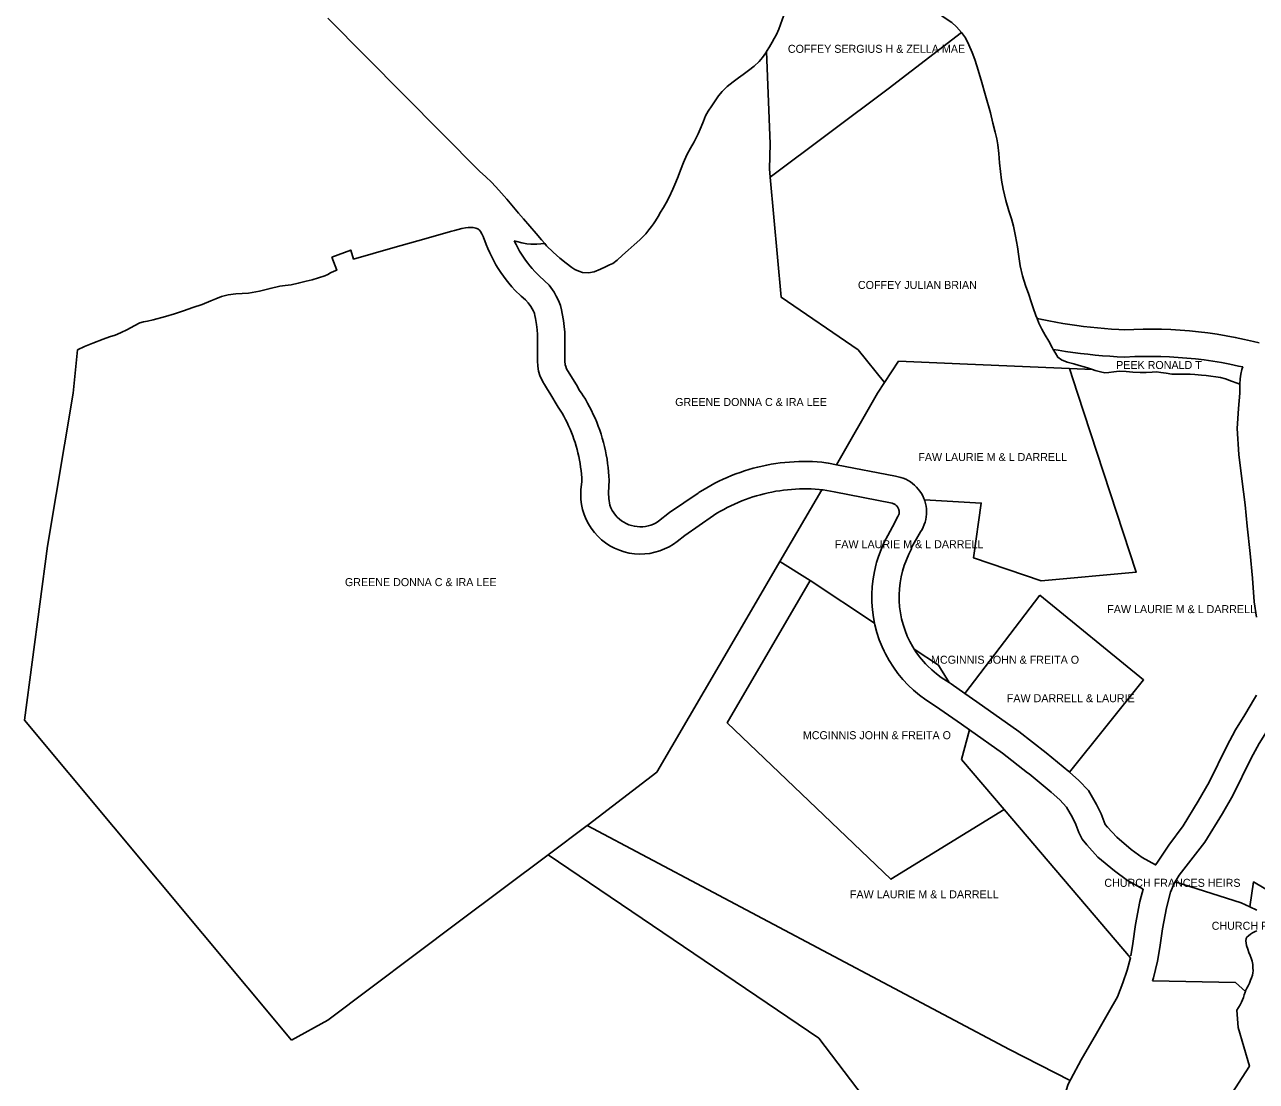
# Model space of a CAD drawing. Extents: x 1249333 to 1254314, y 856599 to 862241.
# Drawn here: x 1249333 to 1252043, y 858486 to 860811 of the extents above; entities that cross this region are included whole.
import ezdxf

# ---------------------------------------------------------------- set-up
doc = ezdxf.new("R2010")
doc.units = 0
doc.layers.add('Old_Level_12', color=7, linetype='Continuous')
doc.layers.add('Old_Level_32', color=7, linetype='Continuous')

msp = doc.modelspace()

# ---------------------------------------------------------------- linework, layer by layer
at = {"layer": 'Old_Level_12'}
for p, q in [((1251407.875, 860064), (1251631.875, 860054.5)), ((1251631.875, 860054.5), (1251682.25, 860052.375)), ((1251087.25, 859787.625), (1250994.875, 859629.563)), ((1249382.625, 859663.688), (1249332.625, 859280.875)), ((1250994.875, 859629.563), (1251061.375, 859587.625)), ((1251061.375, 859587.625), (1251203, 859494.438)), ((1251401.75, 859339.313), (1251567, 859556.063)), ((1251348.375, 859394.438), (1251367.125, 859363.313)), ((1249332.625, 859280.875), (1249920, 858576.75)), ((1251487.875, 859083.75), (1251765.875, 858757.5)), ((1250570.75, 859048.688), (1250484.75, 858984.188)), ((1250286.875, 858835.813), (1250484.75, 858984.188))]:
    msp.add_line(p, q, dxfattribs=at)
for points in [[(1251142.625, 860976.438), (1251152.25, 860975.5), (1251163.5, 860972.063), (1251178.625, 860965.188), (1251190.375, 860958.25), (1251203.125, 860949.625), (1251216.625, 860940.625), (1251228.625, 860932.688), (1251239.875, 860925.25), (1251250.5, 860917.875), (1251261.75, 860909.563), (1251274.375, 860899.25), (1251293.125, 860882.5), (1251308.5, 860867.688), (1251325.875, 860851.688), (1251335.5, 860843.313), (1251344.375, 860835.875), (1251353.125, 860829.313), (1251363, 860822.75), (1251373.125, 860815.563), (1251383.5, 860806.125), (1251394.25, 860794.188)], [(1251026.125, 860872.813), (1251025.25, 860871.688), (1251017.875, 860860.875), (1251009.625, 860846.875), (1251005.125, 860837.563), (1251002.375, 860829.625), (1251000, 860822.125), (1250996.375, 860811.813), (1250992, 860800.938), (1250986.875, 860789.688), (1250982.25, 860780.688), (1250977.5, 860772.438), (1250971.625, 860762.5), (1250965.25, 860751.75)], [(1250000, 860825.125), (1250334.25, 860488.25), (1250346.875, 860476.875), (1250360.5, 860463.75), (1250376.25, 860447.063), (1250394, 860426.813), (1250408.25, 860409.625), (1250419.375, 860396.25), (1250430.375, 860383.813), (1250444.25, 860368.063), (1250458.25, 860351.875), (1250469.75, 860337.875), (1250477.125, 860329.5)], [(1251394.25, 860794.188), (1251233.125, 860670.188), (1250973.625, 860475.375)], [(1251394.25, 860794.188), (1251402.875, 860782.125), (1251410.625, 860766.938), (1251417.875, 860749.563), (1251423.5, 860734.5), (1251428.25, 860720.563), (1251437.75, 860689.313), (1251447.5, 860655.563), (1251457.875, 860617), (1251463.5, 860594.5), (1251468.375, 860574.563), (1251471.875, 860560.188), (1251474.125, 860546.563), (1251476.375, 860527.563), (1251478.25, 860507.438), (1251480.125, 860487.75), (1251482.5, 860469.25), (1251486.25, 860449.438), (1251492.25, 860424.375), (1251498.75, 860401.25), (1251504.25, 860383.875), (1251508.75, 860367.438), (1251511, 860356.875), (1251513.375, 860345.5), (1251517.375, 860322.313), (1251520.5, 860300.688), (1251523.75, 860280.188), (1251528.625, 860258.688), (1251535.375, 860237.188), (1251542.5, 860217.125), (1251547.875, 860201.125), (1251552.125, 860187.75), (1251557.875, 860171.125), (1251560.5, 860164.688)], [(1250477.125, 860329.5), (1250481.375, 860324.5), (1250495.75, 860310.313), (1250510.75, 860297.375), (1250524.375, 860286.5), (1250536.625, 860277.125), (1250543.5, 860272.563), (1250551.875, 860268.438), (1250560.625, 860265.5), (1250573.125, 860264.688), (1250585.75, 860267.563), (1250599.75, 860273.125), (1250610.625, 860278), (1250620, 860282.375), (1250627, 860285.875), (1250636.75, 860293), (1250648.5, 860303.75), (1250660.5, 860315.063), (1250673.625, 860326.438), (1250686.125, 860337.375), (1250699.375, 860351.063), (1250706.25, 860359.313), (1250712.125, 860366.75), (1250716.5, 860372.688), (1250721, 860379.688), (1250726.5, 860388.813), (1250732.125, 860398.25), (1250738.5, 860408.75), (1250744.5, 860419.063), (1250750.875, 860431.438), (1250759.125, 860448.938), (1250765.875, 860464.25), (1250770.875, 860477), (1250776.125, 860491.125), (1250782.75, 860508), (1250790.125, 860524.625), (1250797.75, 860539.25), (1250805.75, 860553.625), (1250814.5, 860571), (1250821.125, 860586.125), (1250826.375, 860599.125), (1250831.25, 860610.188), (1250837.125, 860620.688), (1250844.75, 860632.375), (1250852.5, 860643.75), (1250859.625, 860654.188), (1250867.625, 860664.125), (1250878.875, 860674.938), (1250892, 860685.688), (1250903.25, 860693.938), (1250914, 860701.375), (1250925.875, 860709.938), (1250938, 860719.563), (1250948.875, 860729.75), (1250956.75, 860739), (1250963.875, 860749.5), (1250965.25, 860751.75)], [(1250965.25, 860751.75), (1250973.625, 860548.625), (1250972, 860493.813), (1250973.625, 860475.375)], [(1250973.625, 860475.375), (1250997.625, 860211.125), (1251167.125, 860095.563), (1251225, 860023.375)], [(1250008.625, 860299.438), (1250050.25, 860315.188), (1250056.375, 860295.313), (1250143.125, 860319.938), (1250197.75, 860335.5), (1250272.875, 860356.813), (1250278.5, 860358.25), (1250286.625, 860360.688), (1250294.75, 860362.563), (1250303, 860363.938), (1250308.875, 860364.75), (1250313.125, 860364.75), (1250320, 860364.438), (1250325.375, 860363.125), (1250329.625, 860361.5), (1250333.375, 860358.813), (1250335.625, 860356.313), (1250338.875, 860350.813), (1250342.25, 860343.75), (1250342.5, 860343.125), (1250345.5, 860335.75), (1250348.5, 860327.563), (1250352.25, 860318.25), (1250356.25, 860309.188), (1250360.5, 860300.25)], [(1250477.125, 860329.5), (1250459.75, 860328.188), (1250446.625, 860327.875), (1250438.125, 860328.938), (1250427.125, 860331.375), (1250415.875, 860334.313), (1250410.125, 860335.813)], [(1250487, 860237.875), (1250465.625, 860258.063), (1250460.75, 860262.625), (1250455.25, 860268.25), (1250449.875, 860274.25), (1250444.5, 860280.375), (1250439.625, 860286.563), (1250434.875, 860292.938), (1250430.25, 860299.5), (1250426, 860306.188), (1250421.875, 860313), (1250417.875, 860320), (1250414.25, 860327.125), (1250410.75, 860334.313), (1250410.125, 860335.813)], [(1250008.625, 860299.438), (1250019.625, 860270.563), (1250014.125, 860268.375), (1250006, 860264.688), (1250000, 860261.438), (1249993.125, 860258.75), (1249979.625, 860254.313), (1249965.625, 860249.688), (1249952.125, 860246.375), (1249934.75, 860241.938), (1249919, 860238.688), (1249906.125, 860237.063), (1249894.375, 860235.563), (1249872.875, 860230.875), (1249849.625, 860224.938), (1249825.25, 860220.375), (1249811, 860219.25), (1249797.25, 860218.5), (1249780.875, 860216.375), (1249765.75, 860212.688), (1249753.625, 860208.125), (1249742.375, 860203.188), (1249723.375, 860195.688), (1249703, 860188.563), (1249682.5, 860181.563), (1249662.75, 860174.875), (1249642.875, 860168.875), (1249615.25, 860161.563), (1249603.125, 860158.813), (1249594.125, 860156.938), (1249586.5, 860154.75), (1249573.375, 860148.688), (1249559.125, 860140.625), (1249543.625, 860132.75), (1249531.5, 860127.938), (1249519.75, 860124.063), (1249505.625, 860119.188), (1249483, 860110.438)], [(1250360.5, 860300.25), (1250365.125, 860291.5), (1250369.875, 860282.875), (1250375, 860274.313), (1250380.5, 860266), (1250386.125, 860257.813), (1250392.125, 860249.813), (1250398.5, 860242), (1250404.875, 860234.5), (1250411.5, 860227.25), (1250425.5, 860213.375), (1250434.625, 860205.688), (1250440.75, 860199.375), (1250446.875, 860190.75), (1250449.625, 860185.688), (1250452.25, 860180.563), (1250453.625, 860177.688), (1250454.375, 860175.625), (1250455.5, 860171.063), (1250456.75, 860164.625), (1250458.75, 860151.688), (1250460.375, 860139.813), (1250461.375, 860129.438), (1250461.375, 860071.5), (1250462.125, 860059.813), (1250463.75, 860048.5), (1250466.625, 860038.938), (1250473, 860025.25), (1250476.75, 860018.938), (1250483.375, 860008.563), (1250488.5, 860000), (1250507, 859969.75), (1250511.25, 859963.063), (1250515.25, 859956.313), (1250519.125, 859949.438), (1250522.875, 859942.5), (1250526.5, 859935.438), (1250529.75, 859928.313), (1250533, 859921.063), (1250536, 859913.75), (1250538.875, 859906.5), (1250541.5, 859899.063), (1250544, 859891.5), (1250546.375, 859883.875), (1250548.5, 859876.25), (1250550.375, 859868.75), (1250552.125, 859861), (1250553.75, 859853.125), (1250555.125, 859845.5), (1250556.25, 859837.563), (1250557.375, 859829.688), (1250558.125, 859821.875), (1250558.75, 859813.938), (1250559.125, 859805.938), (1250556.75, 859787.813), (1250556.375, 859777.75), (1250556.875, 859766.375), (1250558.125, 859755.125), (1250560.625, 859744), (1250564, 859733.063), (1250568.375, 859722.563), (1250573.5, 859712.563), (1250579.5, 859703), (1250586.375, 859693.813), (1250593.875, 859685.438), (1250602.125, 859677.688), (1250611.125, 859670.625), (1250620.75, 859664.313), (1250630.875, 859658.938), (1250641.375, 859654.5), (1250652.125, 859650.938), (1250663.125, 859648.375), (1250674.5, 859646.75), (1250685.875, 859646.125), (1250697.125, 859646.438), (1250708.5, 859647.688), (1250719.625, 859650), (1250730.5, 859653.25), (1250741, 859657.313), (1250751.25, 859662.375), (1250760.875, 859668.25), (1250768.375, 859673.563), (1250785.625, 859687), (1250848.875, 859731.188), (1250856.25, 859735.813), (1250863.75, 859740.25), (1250871.375, 859744.5), (1250879, 859748.563), (1250886.75, 859752.438), (1250894.625, 859756.125), (1250902.625, 859759.625), (1250910.625, 859762.938), (1250918.75, 859766.063), (1250926.875, 859769), (1250935.125, 859771.75), (1250943.375, 859774.313), (1250951.75, 859776.688), (1250960.125, 859778.875), (1250968.625, 859780.875), (1250977.125, 859782.688)], [(1251119.375, 859842.5), (1251101.625, 859846.125), (1251096.125, 859847.25), (1251086.625, 859848.188), (1251076.5, 859848.938), (1251066.375, 859849.5), (1251056.25, 859849.813), (1251046.125, 859849.875), (1251036, 859849.688), (1251025.875, 859849.25), (1251015.75, 859848.625), (1251005.625, 859847.75), (1250995.625, 859846.625), (1250985.625, 859845.25), (1250975.625, 859843.625), (1250965.625, 859841.813), (1250955.75, 859839.75), (1250945.875, 859837.438), (1250936.125, 859834.875), (1250926.375, 859832.125), (1250916.75, 859829.125), (1250907.125, 859825.938), (1250897.625, 859822.5), (1250888.25, 859818.813), (1250878.875, 859814.938), (1250869.625, 859810.813), (1250860.5, 859806.5), (1250851.5, 859801.938), (1250842.625, 859797.188), (1250833.75, 859792.25), (1250825, 859787.063), (1250818.5, 859783), (1250816.5, 859781.563), (1250814.625, 859780.313), (1250751.75, 859737.375), (1250727.625, 859718.25), (1250722.25, 859715), (1250716.75, 859712.313), (1250711, 859710), (1250705.125, 859708.25), (1250699, 859707.063), (1250692.875, 859706.313), (1250686.625, 859706.125), (1250680.5, 859706.5), (1250674.375, 859707.375), (1250668.375, 859708.813), (1250662.375, 859710.75), (1250656.625, 859713.188), (1250651.25, 859716.063), (1250646.125, 859719.375), (1250641.375, 859723.188), (1250636.875, 859727.438), (1250632.625, 859732.063), (1250629, 859736.875), (1250625.75, 859742.188), (1250622.875, 859747.813), (1250620.5, 859753.563), (1250617.875, 859768.313), (1250617.25, 859780.563), (1250619, 859808.563), (1250618.375, 859817.813), (1250617.75, 859827.125), (1250616.75, 859836.563), (1250615.625, 859845.813), (1250614.25, 859855), (1250612.625, 859864.375), (1250610.75, 859873.5), (1250608.75, 859882.625), (1250606.375, 859891.875), (1250603.75, 859900.875), (1250601.125, 859909.75), (1250598.125, 859918.563), (1250595, 859927.375), (1250591.625, 859936.25), (1250587.875, 859944.938), (1250584.125, 859953.438), (1250580, 859961.938), (1250575.875, 859970.25), (1250571.375, 859978.563), (1250566.75, 859986.688), (1250561.75, 859994.688), (1250557.75, 860000), (1250553.25, 860007), (1250549.125, 860014.625), (1250525.375, 860054.125), (1250523.25, 860059.25), (1250522.125, 860062.625), (1250521.625, 860070.5), (1250521.25, 860083.438), (1250521.25, 860134.25), (1250519.875, 860146.688), (1250518.25, 860160.313), (1250515.75, 860175.25), (1250514, 860183.938), (1250511.875, 860192.875), (1250509.125, 860200.563), (1250506.25, 860206.813), (1250502.625, 860213.938), (1250497.625, 860222.75), (1250487, 860237.875)], [(1251560.5, 860164.688), (1251564.625, 860154.375), (1251571.125, 860140.813), (1251578.25, 860128.063), (1251586.25, 860114.375), (1251593.875, 860101), (1251596.375, 860096.5)], [(1252049.375, 860110.813), (1252036.625, 860114.063), (1252016.875, 860118.625), (1251996.875, 860122.813), (1251976.75, 860126.563), (1251956.625, 860129.875), (1251936.25, 860132.813), (1251916.125, 860135.25), (1251895.75, 860137.313), (1251875.25, 860138.938), (1251854.875, 860140.063), (1251834.5, 860140.875), (1251814.125, 860141.188), (1251793.75, 860141.063), (1251773.375, 860140.563), (1251754, 860139.563), (1251740.25, 860140.25), (1251724.75, 860141.25), (1251709.375, 860142.375), (1251693.875, 860143.813), (1251678.5, 860145.375), (1251663.125, 860147.125), (1251647.875, 860149.188), (1251632.5, 860151.375), (1251617.125, 860153.813), (1251602, 860156.375), (1251586.75, 860159.25), (1251571.5, 860162.313), (1251560.5, 860164.688)], [(1249483, 860110.438), (1249464.625, 860102.563), (1249449.25, 860095.688)], [(1249449.25, 860095.688), (1249439.375, 860000), (1249382.625, 859663.688)], [(1251596.375, 860096.5), (1251607.375, 860094.563), (1251623.5, 860092), (1251639.625, 860089.688), (1251655.875, 860087.625), (1251672, 860085.75), (1251688.125, 860084.063), (1251704.375, 860082.625), (1251720.75, 860081.375), (1251737, 860080.375)], [(1251596.375, 860096.5), (1251600.875, 860088.5), (1251606.25, 860079.188), (1251614.125, 860073.375), (1251627.125, 860068.75), (1251641.375, 860064.813), (1251653.125, 860061.438), (1251664, 860058.063), (1251675.75, 860054.375), (1251682.25, 860052.375)], [(1251737, 860080.375), (1251753.125, 860079.625), (1251775.625, 860080.563), (1251794.75, 860081.063), (1251813.875, 860081.188), (1251833, 860080.875), (1251852.125, 860080.188), (1251871.25, 860079.063), (1251890.25, 860077.563), (1251909.375, 860075.625), (1251928.5, 860073.313), (1251947.375, 860070.625), (1251966.25, 860067.438), (1251985.125, 860063.938), (1252003.875, 860060), (1252013.25, 860057.813), (1252011.375, 860052.375), (1252009.125, 860042.063), (1252007.375, 860031.5), (1252006.625, 860020)], [(1251225, 860023.375), (1251256, 860070.438), (1251407.875, 860064)], [(1251631.875, 860054.5), (1251649.75, 860000), (1251778.875, 859606.688), (1251570, 859587.313), (1251420.375, 859637.875), (1251437.75, 859758.25), (1251312.625, 859765.188)], [(1251682.25, 860052.375), (1251688.5, 860050.438), (1251700.375, 860047.063), (1251709.75, 860045.188), (1251718.375, 860045.5), (1251729.625, 860047), (1251741.375, 860048.375), (1251756.875, 860048.25), (1251771.5, 860046.75), (1251787.375, 860045.563), (1251801, 860045.813), (1251813.625, 860046.5), (1251823.375, 860046.813), (1251832.625, 860045.813), (1251844.625, 860043.938), (1251856.875, 860042.375), (1251866.875, 860041.875), (1251876.625, 860041.938), (1251887.25, 860042), (1251897.875, 860041.688), (1251907.75, 860041.25), (1251914.875, 860040.813), (1251922.25, 860040.125), (1251932.5, 860038.875), (1251943.25, 860037.563), (1251954.25, 860036.125), (1251964.5, 860034.375), (1251975.25, 860031.625), (1251988.625, 860026.875), (1252001, 860022), (1252006.625, 860020)], [(1251225, 860023.375), (1251209.25, 860000), (1251119.375, 859842.5)], [(1252006.625, 860020), (1252006.75, 860009.813), (1252006.875, 860000), (1252003.875, 859966.438), (1252000.75, 859922.5), (1252005, 859864.938), (1252011.125, 859811.75), (1252018.375, 859754.813), (1252023, 859707.813), (1252029.875, 859647.188), (1252034.625, 859593.375), (1252038.625, 859540.813), (1252043.75, 859507)], [(1251312.625, 859765.188), (1251311.375, 859768.75), (1251308.875, 859774.125), (1251306, 859779.313), (1251302.75, 859784.25), (1251299.25, 859788.938), (1251295.375, 859793.375), (1251291.125, 859797.5), (1251286.625, 859801.313), (1251281.875, 859804.813), (1251276.875, 859807.938), (1251271.625, 859810.688), (1251266.25, 859813), (1251260.625, 859814.938), (1251254.875, 859816.438), (1251249.125, 859817.5), (1251119.375, 859842.5)], [(1250977.125, 859782.688), (1250985.625, 859784.25), (1250994.25, 859785.625), (1251002.875, 859786.813), (1251011.5, 859787.813), (1251020.125, 859788.563), (1251028.75, 859789.125), (1251037.5, 859789.5), (1251046.25, 859789.688), (1251055, 859789.625), (1251063.75, 859789.375), (1251072.375, 859788.938), (1251081, 859788.25), (1251087.25, 859787.625)], [(1251087.25, 859787.625), (1251089.625, 859787.375), (1251114, 859782.75)], [(1251114, 859782.75), (1251241.875, 859757.875), (1251243.25, 859757.5), (1251244.625, 859757), (1251246, 859756.438), (1251247.25, 859755.75), (1251248.5, 859755), (1251249.75, 859754.125), (1251250.875, 859753.188), (1251251.875, 859752.125), (1251252.875, 859751), (1251253.75, 859749.813), (1251254.5, 859748.563), (1251255.25, 859747.25), (1251255.875, 859745.875), (1251256.375, 859744.5), (1251256.75, 859743.063), (1251257, 859741.625), (1251257.25, 859738.75), (1251257.25, 859737.25), (1251257.125, 859735.813), (1251256.875, 859734.375), (1251256.5, 859732.938), (1251256, 859731.563), (1251254.375, 859728.625), (1251242.5, 859705.813), (1251232.375, 859687.188), (1251224.5, 859672), (1251217.625, 859656.563), (1251211.625, 859640.688), (1251207.625, 859627.625), (1251206.625, 859624.375), (1251202.75, 859607.938), (1251199.75, 859591.375), (1251197.875, 859574.5), (1251197, 859557.5), (1251197.125, 859540.5), (1251198.375, 859523.563), (1251200.625, 859506.813), (1251203, 859494.438)], [(1251290.125, 859437.188), (1251287, 859442.125), (1251280.625, 859453.75), (1251274.875, 859465.813), (1251270, 859478.188), (1251265.75, 859490.813), (1251262.375, 859503.563), (1251259.875, 859516.563), (1251258.125, 859529.813), (1251257.125, 859543), (1251257.125, 859545.625), (1251257, 859556.25), (1251257.625, 859569.5), (1251259.25, 859582.625), (1251261.5, 859595.813), (1251264.625, 859608.75), (1251268.375, 859621.313), (1251273.125, 859633.813), (1251278.5, 859646), (1251284.625, 859657.688), (1251284.375, 859660.938), (1251304.25, 859694.813), (1251307.625, 859700.063), (1251310.25, 859705.375), (1251312.5, 859710.875), (1251314.375, 859716.5), (1251315.75, 859722.25), (1251316.75, 859728.063), (1251317.25, 859733.938), (1251317.375, 859739.875), (1251317, 859745.813), (1251316.25, 859751.688), (1251315, 859757.5), (1251313.375, 859763.188), (1251312.625, 859765.188)], [(1250994.875, 859629.563), (1250932.125, 859522.375), (1250723.75, 859166.188), (1250572.75, 859050.25), (1250570.75, 859048.688)], [(1251061.375, 859587.625), (1250878.875, 859274.5), (1251239.125, 858930.438), (1251487.875, 859083.75)], [(1251567, 859556.063), (1251794.875, 859369.375), (1251632.25, 859166.188)], [(1251203, 859494.438), (1251203.875, 859490.188), (1251208.25, 859473.688), (1251213.5, 859457.563), (1251219.875, 859441.813), (1251224.25, 859432.563), (1251227.125, 859426.5), (1251235.25, 859411.625), (1251244.375, 859397.25), (1251254.375, 859383.5), (1251265.125, 859370.438), (1251276.625, 859358), (1251289, 859346.313), (1251302, 859335.375), (1251315.625, 859325.313), (1251336.875, 859311.563), (1251394, 859271.5), (1251411.625, 859259.188)], [(1251290.125, 859437.188), (1251343.875, 859401.813), (1251348.375, 859394.438)], [(1251367.125, 859363.313), (1251349.875, 859374.563), (1251339.25, 859382.5), (1251329, 859391.063), (1251319.375, 859400.25), (1251315.375, 859404.625), (1251310.375, 859409.938), (1251301.875, 859420.25), (1251294.125, 859431), (1251290.125, 859437.188)], [(1251401.75, 859339.313), (1251371.375, 859360.563), (1251367.125, 859363.313)], [(1251632.25, 859166.188), (1251630.5, 859167.75), (1251580.875, 859208.938), (1251520.625, 859256), (1251428.125, 859320.813), (1251401.75, 859339.313)], [(1252043.5, 859335.938), (1252041.375, 859332), (1252039.125, 859328.125), (1252017.625, 859292.188), (1251997.25, 859259.188), (1251977.875, 859223.375), (1251939.125, 859144.563), (1251915.375, 859102.75), (1251882.125, 859048.375), (1251850.625, 859005.688), (1251824, 858966.25), (1251821.375, 858962.063), (1251792.125, 858978.438), (1251768, 858996.375), (1251735.875, 859023), (1251715.625, 859045.125), (1251710.75, 859051.125), (1251708.125, 859056.688), (1251701.5, 859074.375), (1251691.625, 859094.813), (1251673.5, 859125.5), (1251652.625, 859148.063), (1251632.25, 859166.188)], [(1251864.75, 858925.188), (1251873, 858939.75), (1251930.125, 859012.125), (1251968.875, 859075.25), (1251991.375, 859115.063), (1252031.875, 859197), (1252049.25, 859229.188), (1252068.875, 859261.063), (1252076.875, 859274.438)], [(1251487.875, 859083.75), (1251394.125, 859193.813), (1251411.625, 859259.188)], [(1251411.625, 859259.188), (1251484.875, 859207.75), (1251539.75, 859164.938), (1251543.25, 859162.188), (1251591.375, 859122.313), (1251610.5, 859105.188), (1251625.125, 859089.438), (1251638.625, 859066.5), (1251646.25, 859050.688), (1251652.875, 859033.125), (1251659.625, 859019), (1251670, 859006.063), (1251694.375, 858979.375), (1251731, 858949.188), (1251759.375, 858928), (1251794.25, 858908.563), (1251789.875, 858892.5), (1251786.875, 858881.375), (1251777.25, 858831.25), (1251771.25, 858789.5), (1251767, 858762.188)], [(1252028.875, 858869.563), (1252037.125, 858924.688), (1252192.25, 858832.625), (1252241.625, 858851.188), (1252496.125, 859020.25), (1252732, 859073.375)], [(1250570.75, 859048.688), (1251500, 858555.875), (1251633.5, 858487.813)], [(1250484.75, 858984.188), (1251080.125, 858580.625), (1251261.875, 858342.75), (1251350.125, 858227.063), (1251408.875, 858165.875), (1251422.875, 858157.125)], [(1251814.375, 858707.188), (1251816.5, 858713.313), (1251826, 858750.313), (1251830.5, 858780.625), (1251836.5, 858821.25), (1251845.375, 858867.875), (1251854.625, 858902.438), (1251862.5, 858921.125), (1251864.75, 858925.188)], [(1251864.75, 858925.188), (1252009.75, 858878.625), (1252028.875, 858869.563)], [(1252044.25, 858862.25), (1252028.875, 858869.563)], [(1249920, 858576.75), (1250000, 858620.563), (1250286.875, 858835.813)], [(1252019, 858683.813), (1252020.125, 858686.625), (1252022.25, 858691.125), (1252024.875, 858696.313), (1252027.75, 858702.125), (1252030.5, 858708.25), (1252032.75, 858713.875), (1252034.625, 858719.313), (1252035.75, 858724.438), (1252036.125, 858729.063), (1252035.75, 858735.5), (1252035.125, 858743), (1252033.875, 858750.563), (1252032.125, 858757.063), (1252029.625, 858763.063), (1252026.875, 858769.5), (1252024.125, 858776.625), (1252021.75, 858784.625), (1252020.75, 858790.063), (1252020.375, 858795.375), (1252020.875, 858799.938), (1252022.5, 858803.063), (1252025.875, 858806.125), (1252030.125, 858809.625), (1252035, 858813), (1252040.5, 858815.813), (1252044.375, 858817.125)], [(1251765.875, 858757.5), (1251759, 858730.438), (1251749.625, 858702.938), (1251737.375, 858671.5), (1251718, 858637.438), (1251691.75, 858591.25), (1251657.625, 858532.875), (1251634.875, 858490.313), (1251633.5, 858487.813)], [(1251814.375, 858707.188), (1251997.25, 858703.438), (1252019, 858683.813)], [(1251826.75, 858365.938), (1251832.375, 858366.25), (1251871.75, 858368.688), (1251960.125, 858318.688), (1251981.25, 858446.25), (1252027.75, 858519.438), (1252003.25, 858604.25), (1252000.125, 858642.625), (1252003.875, 858648.375), (1252007.375, 858654.125), (1252010.5, 858659.813), (1252012.875, 858665.438), (1252014.625, 858670.688), (1252016.5, 858676.563), (1252018.375, 858682.125), (1252019, 858683.813)], [(1251633.5, 858487.813), (1251629.125, 858479.563), (1251619.625, 858449.688), (1251608.25, 858423.813), (1251604.375, 858414.75), (1251593.125, 858388.313), (1251571.25, 858354.25), (1251546.625, 858325.688), (1251523.625, 858304.938), (1251520.5, 858302.125), (1251508.75, 858290.688), (1251493.625, 858274.125), (1251478, 858253.375), (1251471.75, 858242.938)]]:
    msp.add_lwpolyline(points, dxfattribs=at)

# ---------------------------------------------------------------- texts
at = {"layer": 'Old_Level_32'}
for s, p in [('COFFEY SERGIUS H & ZELLA MAE', (1251012.25, 860749.188)), ('COFFEY JULIAN BRIAN', (1251166.375, 860229.563)), ('PEEK RONALD T', (1251734.625, 860053.438)), ('GREENE DONNA C & IRA LEE', (1250764.25, 859971.938)), ('FAW LAURIE M & L DARRELL', (1251299.25, 859850.875)), ('FAW LAURIE M & L DARRELL', (1251115.5, 859659.125)), ('GREENE DONNA C & IRA LEE', (1250037.5, 859575.625)), ('FAW LAURIE M & L DARRELL', (1251715.125, 859516.188)), ('MCGINNIS JOHN & FREITA O', (1251327.25, 859404.813)), ('FAW DARRELL & LAURIE', (1251494.125, 859320.188)), ('MCGINNIS JOHN & FREITA O', (1251045.25, 859238.75)), ('CHURCH FRANCES HEIRS', (1251708.625, 858913.875)), ('FAW LAURIE M & L DARRELL', (1251148.75, 858888.625)), ('CHURCH FRANCES HEIRS', (1251944.875, 858819.375))]:
    msp.add_text(s, height=17.61477, dxfattribs=at).set_placement(p)

doc.saveas('drawing.dxf')
